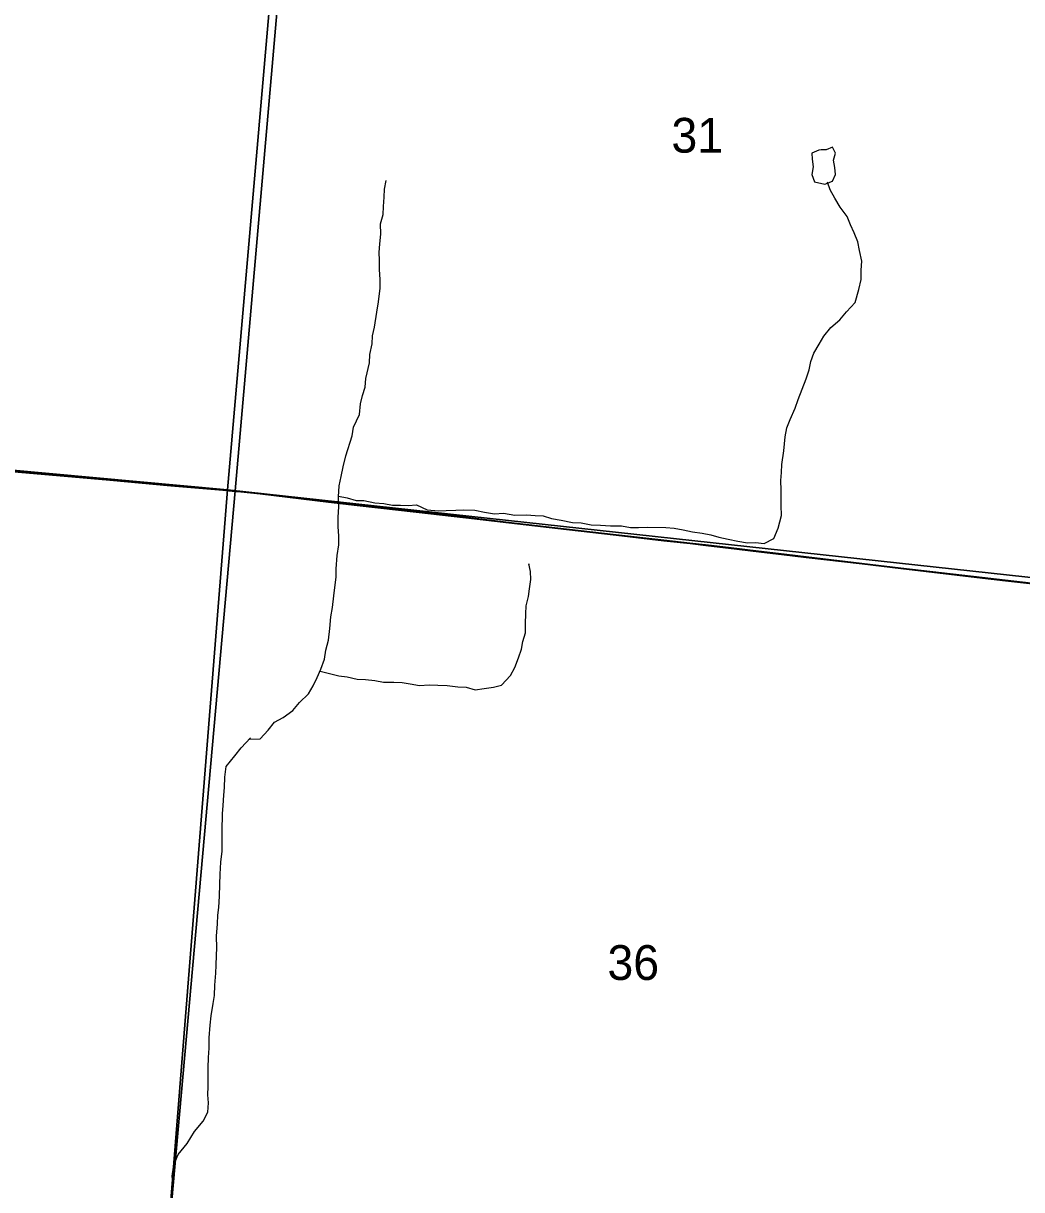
# Model space of a CAD drawing. Extents: x 0 to 1067, y 0 to 440.
# Drawn here: x 799.446 to 800.649, y 352.868 to 354.272 of the extents above; entities that cross this region are included whole.
import ezdxf

# ---------------------------------------------------------------- set-up
doc = ezdxf.new("R2010")
doc.units = 0
for name, color, linetype in [('GM_X_County_Road', 7, 'Continuous'), ('GM_X_Minor_Lake', 7, 'Continuous'), ('GM_X_Minor_River', 7, 'Continuous'), ('GM_X_Section', 7, 'Continuous'), ('GM_X_Section_Text', 7, 'Continuous'), ('GM_X_Township_Road', 7, 'Continuous')]:
    doc.layers.add(name, color=color, linetype=linetype)

msp = doc.modelspace()

# ---------------------------------------------------------------- linework, layer by layer
at = {"layer": 'GM_X_County_Road'}
for points in [[(799.0462, 353.7669), (799.0514, 353.7664), (799.0903, 353.7628), (799.1386, 353.7583), (799.1695, 353.7554), (799.2066, 353.7518), (799.2331, 353.7491), (799.2604, 353.7462), (799.2719, 353.7448), (799.2881, 353.7435), (799.326, 353.7415), (799.3372, 353.7408), (799.3978, 353.7359), (799.4356, 353.7325), (799.5049, 353.7264), (799.5507, 353.7223), (799.6243, 353.7157), (799.6485, 353.7137), (799.6868, 353.7102), (799.7019, 353.7088)], [(799.7019, 353.7088), (799.7087, 353.7082), (799.732, 353.7058), (799.7647, 353.7018), (799.814, 353.6959), (799.8486, 353.6919), (799.9196, 353.6839), (799.9795, 353.6771), (800.0313, 353.6709), (800.101, 353.6629), (800.1609, 353.656), (800.2183, 353.6495), (800.2498, 353.6459), (800.272, 353.6434), (800.2961, 353.6406), (800.3325, 353.6362), (800.3633, 353.6325), (800.3898, 353.6294), (800.4569, 353.6215), (800.5038, 353.6159), (800.6019, 353.6045), (800.6297, 353.6013), (800.7167, 353.5914), (800.7506, 353.5877)]]:
    msp.add_lwpolyline(points, dxfattribs=at)
at = {"layer": 'GM_X_Minor_Lake'}
for points in [[(800.4123, 354.0788), (800.4214, 354.0821), (800.425, 354.0903), (800.4243, 354.0987), (800.4226, 354.1074), (800.425, 354.1161), (800.4213, 354.1234), (800.4137, 354.1201), (800.4079, 354.1199)], [(800.4079, 354.1199), (800.405, 354.1198), (800.3966, 354.1162), (800.3969, 354.1086), (800.3979, 354.0995), (800.3966, 354.0904), (800.3995, 354.0816), (800.4123, 354.0788)]]:
    msp.add_lwpolyline(points, dxfattribs=at)
at = {"layer": 'GM_X_Minor_River'}
for points in [[(799.7189, 353.4107), (799.732, 353.4109), (799.7414, 353.4213), (799.7493, 353.431), (799.7597, 353.4368), (799.771, 353.4452), (799.7792, 353.4548), (799.7901, 353.4652), (799.7957, 353.4749), (799.8006, 353.4847), (799.8051, 353.4948), (799.8092, 353.5069), (799.811, 353.5175), (799.814, 353.5296), (799.8156, 353.5436), (799.8171, 353.558), (799.819, 353.569), (799.8205, 353.5831), (799.8235, 353.6058), (799.8234, 353.6154), (799.8246, 353.6317), (799.8265, 353.6446), (799.8268, 353.6549), (799.826, 353.6667), (799.8259, 353.6777), (799.8267, 353.6903), (799.8263, 353.7021), (799.8271, 353.7154), (799.8293, 353.7268), (799.8319, 353.7385), (799.8349, 353.7517), (799.8425, 353.7759), (799.8443, 353.7861), (799.8516, 353.8015), (799.8527, 353.8144), (799.8553, 353.8242), (799.8582, 353.8344), (799.8593, 353.8447), (799.8636, 353.8636), (799.8639, 353.8735), (799.8666, 353.8864), (799.8672, 353.8962), (799.8694, 353.9065), (799.8722, 353.9247), (799.8745, 353.9372), (799.8765, 353.9535), (799.8764, 353.9638), (799.8756, 353.976), (799.8756, 353.987), (799.8751, 353.9965), (799.8762, 354.0068), (799.8773, 354.0186), (799.8769, 354.0311), (799.8799, 354.0421), (799.8805, 354.0516), (799.8812, 354.063), (799.8815, 354.0725), (799.8837, 354.0831)], [(799.8263, 353.7029), (799.8365, 353.701), (799.8474, 353.6977), (799.8569, 353.6978), (799.8701, 353.6951), (799.8807, 353.6944), (799.8913, 353.6922), (799.9008, 353.6923), (799.9102, 353.692), (799.9201, 353.6928), (799.9332, 353.6867), (799.9465, 353.6856), (799.956, 353.686), (799.9674, 353.6861), (799.9769, 353.6866), (799.9905, 353.6862), (800.0022, 353.6839), (800.0143, 353.682), (800.0249, 353.6825), (800.0385, 353.6801), (800.0526, 353.6805), (800.0632, 353.6798), (800.0727, 353.6795), (800.0828, 353.6762), (800.0945, 353.6743), (800.1081, 353.6712), (800.1187, 353.6709), (800.1308, 353.6686), (800.1418, 353.6683), (800.1539, 353.6672), (800.1672, 353.6672), (800.1778, 353.6653), (800.1876, 353.6654), (800.1983, 353.6659), (800.2206, 353.6652), (800.2305, 353.6645), (800.2414, 353.6627), (800.2527, 353.6601), (800.2645, 353.6586), (800.2746, 353.6564), (800.2844, 353.6538), (800.2957, 353.6512), (800.3074, 353.6489), (800.3191, 353.647), (800.3286, 353.6471), (800.3389, 353.6461), (800.3508, 353.6522), (800.3557, 353.6646), (800.3599, 353.6797), (800.3595, 353.6919), (800.3597, 353.7102), (800.3593, 353.722), (800.3599, 353.7315), (800.3602, 353.741), (800.3626, 353.7577), (800.3642, 353.7744), (800.3664, 353.7854), (800.3702, 353.7952), (800.3762, 353.8091), (800.38, 353.8196), (800.3898, 353.8445), (800.3932, 353.855), (800.3953, 353.8653), (800.3987, 353.8751), (800.4051, 353.8859), (800.411, 353.8956), (800.4193, 353.9061), (800.4302, 353.9153), (800.4381, 353.9249), (800.4487, 353.9364), (800.4529, 353.9519), (800.4559, 353.964), (800.4559, 353.975), (800.4566, 353.9861), (800.4539, 353.9987), (800.4519, 354.0094), (800.4473, 354.0199), (800.443, 354.0299), (800.4392, 354.0399), (800.4304, 354.0508), (800.4242, 354.062), (800.4185, 354.0717), (800.4153, 354.081)], [(799.804, 353.4924), (799.8155, 353.4895), (799.8265, 353.4869), (799.8367, 353.4855), (799.8487, 353.4828), (799.8586, 353.4825), (799.8699, 353.4811), (799.8805, 353.4792), (799.893, 353.4792), (799.9029, 353.4789), (799.9127, 353.4771), (799.924, 353.4753), (799.9354, 353.4761), (799.946, 353.4757), (799.957, 353.475), (799.9699, 353.4735), (799.9801, 353.4732), (799.991, 353.4698), (800.0017, 353.4714), (800.0131, 353.473), (800.0227, 353.4754), (800.0333, 353.4872), (800.0385, 353.497), (800.043, 353.5086), (800.0467, 353.5188), (800.0481, 353.5283), (800.0515, 353.5385), (800.0514, 353.5499), (800.0521, 353.5613), (800.0524, 353.5712), (800.055, 353.5822), (800.0564, 353.5916), (800.0579, 353.6026), (800.0574, 353.6122), (800.0554, 353.6218), (800.0554, 353.6206)], [(799.6251, 352.8622), (799.6269, 352.8743), (799.6259, 352.8846), (799.6277, 352.8979), (799.6332, 352.9107), (799.6437, 352.9238), (799.6527, 352.9381), (799.6631, 352.9508), (799.6686, 352.9613), (799.6696, 352.9727), (799.6686, 352.9822), (799.6692, 352.9925), (799.669, 353.005), (799.6692, 353.0149), (799.6698, 353.0274), (799.6704, 353.0384), (799.6706, 353.0509), (799.6716, 353.0661), (799.673, 353.0775), (799.6751, 353.0922), (799.6768, 353.1021), (799.6774, 353.1142), (799.6784, 353.129), (799.679, 353.1385), (799.6792, 353.1499), (799.6797, 353.1594), (799.6792, 353.1734), (799.6806, 353.1882), (799.6808, 353.1985), (799.6821, 353.2079), (799.6827, 353.2216), (799.6833, 353.2356), (799.6835, 353.2482), (799.6846, 353.2626), (799.6859, 353.2755), (799.6861, 353.2849), (799.686, 353.3001), (799.6863, 353.3206), (799.6873, 353.3305), (799.6882, 353.343), (799.6888, 353.3525), (799.6894, 353.3646), (799.6908, 353.3775), (799.7012, 353.3903), (799.709, 353.4), (799.7202, 353.4122)]]:
    msp.add_lwpolyline(points, dxfattribs=at)
at = {"layer": 'GM_X_Section'}
for points in [[(798.781, 354.8126), (799.7802, 354.7186), (799.6925, 353.7106), (798.688, 353.8024)], [(799.7802, 354.7186), (800.8205, 354.5819), (800.7452, 353.5961), (799.6925, 353.7106)], [(798.688, 353.8024), (799.6925, 353.7106), (799.6121, 352.7044), (798.6013, 352.7849)], [(799.6925, 353.7106), (800.7452, 353.5961), (800.6794, 352.6083), (799.6121, 352.7044)]]:
    msp.add_lwpolyline(points, close=True, dxfattribs=at)
at = {"layer": 'GM_X_Township_Road'}
for points in [[(799.4354, 353.7331), (799.5047, 353.7269), (799.5505, 353.7229), (799.6241, 353.7162), (799.6483, 353.7142), (799.6866, 353.7107), (799.7017, 353.7093), (799.8752, 355.6984)], [(799.8752, 355.6984), (799.7017, 353.7093), (799.7085, 353.7087), (799.7317, 353.7063), (799.7644, 353.7024), (799.8138, 353.6965), (799.8483, 353.6924), (799.9194, 353.6845), (799.9792, 353.6776), (800.0311, 353.6715), (800.1008, 353.6634), (800.1607, 353.6565), (800.2181, 353.65), (800.2496, 353.6465), (800.2718, 353.6439), (800.2959, 353.6412), (800.3322, 353.6367), (800.363, 353.6331), (800.3895, 353.63), (800.4567, 353.622), (800.5036, 353.6165), (800.6017, 353.6051), (800.6295, 353.6018), (800.7165, 353.5919)], [(799.6113, 352.6978), (799.7017, 353.7093), (799.6866, 353.7107), (799.6483, 353.7142), (799.6241, 353.7162), (799.5505, 353.7229), (799.5047, 353.7269), (799.4354, 353.7331)], [(800.7165, 353.5919), (800.6295, 353.6018), (800.6017, 353.6051), (800.5036, 353.6165), (800.4567, 353.622), (800.3895, 353.63), (800.363, 353.6331), (800.3322, 353.6367), (800.2959, 353.6412), (800.2718, 353.6439), (800.2496, 353.6465), (800.2181, 353.65), (800.1607, 353.6565), (800.1008, 353.6634), (800.0311, 353.6715), (799.9792, 353.6776), (799.9194, 353.6845), (799.8483, 353.6924), (799.8138, 353.6965), (799.7644, 353.7024), (799.7317, 353.7063), (799.7085, 353.7087), (799.7017, 353.7093), (799.6113, 352.6978)]]:
    msp.add_lwpolyline(points, dxfattribs=at)

# ---------------------------------------------------------------- texts
at = {"layer": 'GM_X_Section_Text'}
for s, p in [('31', (800.2273, 354.1166)), ('36', (800.1502, 353.1207))]:
    msp.add_text(s, height=0.04186, rotation=0, dxfattribs=at).set_placement(p)

doc.saveas('drawing.dxf')
